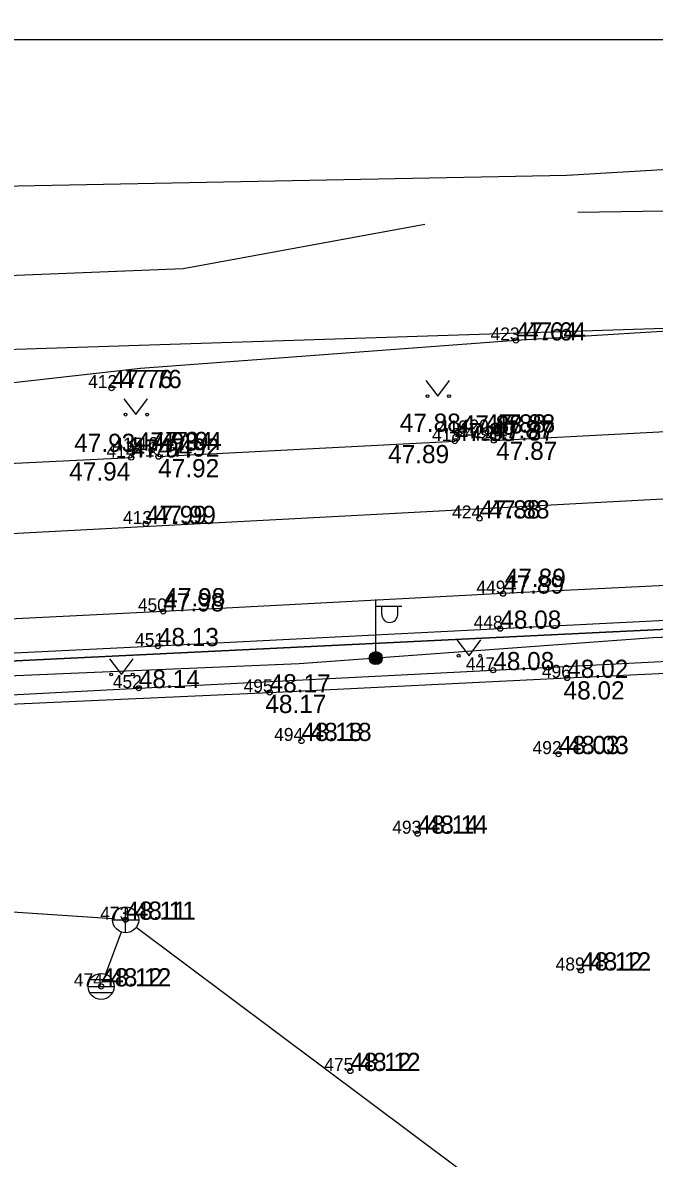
# Model space of a CAD drawing. Extents: x 640876 to 641418, y 6455595 to 6456085.
# Drawn here: x 641173.59 to 641197.83, y 6455977.11 to 6456020.73 of the extents above; entities that cross this region are included whole.
import ezdxf

# ---------------------------------------------------------------- set-up
doc = ezdxf.new("R2010")
doc.units = 0
for name, color, linetype in [('AED', 7, 'Continuous'), ('HALJASTUS', 7, 'Continuous'), ('KKAEV', 7, 'Continuous'), ('KORGUS', 7, 'Continuous'), ('MOOTKORG', 7, 'Continuous'), ('MOOTMPUNKT', 7, 'Continuous'), ('MOOTNR', 7, 'Continuous'), ('MOOTPIIR', 7, 'Continuous'), ('MPKAABEL', 7, 'Continuous'), ('PIIR', 7, 'Continuous'), ('POST', 7, 'Continuous'), ('SKKAEV', 7, 'Continuous'), ('SKTRASS', 7, 'Continuous'), ('TEE', 7, 'Continuous'), ('VEEKOGU', 7, 'Continuous'), ('VORMISTUS', 7, 'Continuous'), ('VTRASS', 7, 'Continuous')]:
    doc.layers.add(name, color=color, linetype=linetype)

msp = doc.modelspace()

# ---------------------------------------------------------------- linework, layer by layer
at = {"layer": 'AED'}
msp.add_lwpolyline([(641160.606, 6455994.253), (641178.047, 6455995.168), (641191.652, 6455995.856), (641207.752, 6455996.687), (641222.341, 6455997.449), (641221.765, 6455994.718), (641219.959, 6455985.906), (641217.708, 6455975.561), (641214.2, 6455967.017), (641207.311, 6455950.541), (641202.719, 6455939.647), (641198.916, 6455930.446)], dxfattribs=at)
at = {"layer": 'HALJASTUS'}
for p, q in [((641189.066, 6456006.992), (641189.53, 6456006.385)), ((641189.53, 6456006.385), (641189.975, 6456006.992)), ((641177.474, 6456006.282), (641177.938, 6456005.675)), ((641177.938, 6456005.675), (641178.383, 6456006.282)), ((641190.26, 6455997.018), (641190.723, 6455996.412)), ((641190.723, 6455996.412), (641191.169, 6455997.018)), ((641176.921, 6455996.297), (641177.385, 6455995.69)), ((641177.385, 6455995.69), (641177.83, 6455996.297))]:
    msp.add_line(p, q, dxfattribs=at)
for centre in [(641189.129, 6456006.385), (641189.957, 6456006.385), (641177.537, 6456005.675), (641178.365, 6456005.675), (641190.322, 6455996.412), (641191.151, 6455996.412), (641176.984, 6455995.69), (641177.813, 6455995.69)]:
    msp.add_circle(centre, 0.055, dxfattribs=at)
at = {"layer": 'KKAEV'}
for p, q in [((641177.541, 6455985.77), (641177.541, 6455986.77)), ((641177.041, 6455986.27), (641178.041, 6455986.27))]:
    msp.add_line(p, q, dxfattribs=at)
msp.add_circle((641177.541, 6455986.27), 0.5, dxfattribs=at)
at = {"layer": 'KORGUS'}
for centre in [(641192.523, 6456008.523), (641177, 6456006.695), (641190.441, 6456004.951), (641191.337, 6456004.985), (641190.176, 6456004.656), (641191.674, 6456004.679), (641177.755, 6456004.027), (641177.971, 6456004.29), (641178.538, 6456004.314), (641178.8, 6456004.062), (641178.314, 6456001.473), (641191.121, 6456001.685), (641192.028, 6455998.799), (641178.983, 6455998.116), (641194.491, 6455995.56), (641183.068, 6455995.004), (641184.29, 6455993.138), (641194.16, 6455992.634), (641188.749, 6455989.577), (641177.541, 6455986.27), (641195.021, 6455984.321), (641176.599, 6455983.71), (641186.165, 6455980.461)]:
    msp.add_circle(centre, 0.1, dxfattribs=at)
at = {"layer": 'MOOTMPUNKT'}
for centre in [(641192.523, 6456008.523), (641177, 6456006.695), (641190.441, 6456004.951), (641191.337, 6456004.985), (641190.176, 6456004.656), (641191.674, 6456004.679), (641177.755, 6456004.027), (641177.971, 6456004.29), (641178.538, 6456004.314), (641178.8, 6456004.062), (641178.314, 6456001.473), (641191.121, 6456001.685), (641192.028, 6455998.799), (641178.983, 6455998.116), (641191.921, 6455997.451), (641178.778, 6455996.781), (641191.652, 6455995.856), (641194.491, 6455995.56), (641178.047, 6455995.168), (641183.068, 6455995.004), (641184.29, 6455993.138), (641194.16, 6455992.634), (641188.749, 6455989.577), (641177.541, 6455986.27), (641195.021, 6455984.321), (641176.599, 6455983.71), (641186.165, 6455980.461)]:
    msp.add_circle(centre, 0.1, dxfattribs=at)
at = {"layer": 'MOOTPIIR'}
msp.add_lwpolyline([(641060.916, 6455895.936), (641100.061, 6455950.482), (641099.586, 6455952.159), (641069.132, 6455984.035), (641066.132, 6455988.623), (641076.463, 6456005.049), (641230.642, 6456010.048), (641237.36, 6455995.24), (641237.24, 6455992.81), (641236.258, 6455990.888), (641229.041, 6455971.315), (641203.026, 6455909.57), (641225.257, 6455906.847), (641239.512, 6455898.491), (641200.195, 6455851.697), (641192.016, 6455859.099), (641169.785, 6455829.138), (641192.025, 6455807.568), (641252.96, 6455758.075), (641231.388, 6455736.74), (641191.474, 6455775.975), (641152.419, 6455787.914), (641136.351, 6455788.307), (641049.066, 6455856.043)], dxfattribs=at)
at = {"layer": 'MPKAABEL'}
msp.add_lwpolyline([(641152.745, 6455994.399), (641157.936, 6455994.715), (641172.717, 6455995.627), (641184.197, 6455996.113), (641197.79, 6455997.111), (641207.568, 6455997.528), (641217.849, 6455998.12), (641221.671, 6455998.134)], dxfattribs=at)
at = {"layer": 'PIIR'}
for points in [[(640981.25, 6456014.49), (641018.11, 6456020.73), (641048.89, 6456017.91), (641071.8, 6456014.51), (641086.43, 6456012.78), (641194.48, 6456014.88), (641224.33, 6456016.64), (641234.96, 6456017.83), (641241.97, 6456004.88), (641237.36, 6455995.24), (641222.58, 6455998.61), (641084.84, 6455991.92), (641061.51, 6455993.34), (640998.61, 6455989.99), (640969.54, 6455988.44)], [(641222.58, 6455998.61), (641237.36, 6455995.24), (641235.34, 6455991.29), (641228.11, 6455971.68), (641220.5, 6455953.19), (641213.41, 6455936.25), (641201.58, 6455908.74), (641224.93, 6455905.88), (641191.87, 6455860.58), (641157.02, 6455885.66), (641160.91, 6455891.99), (641102.26, 6455951.82), (641074.95, 6455979.64), (641084.84, 6455991.92)]]:
    msp.add_lwpolyline(points, close=True, dxfattribs=at)
at = {"layer": 'POST'}
for p, q in [((641187.144, 6455996.571), (641187.144, 6455998.571)), ((641187.144, 6455998.321), (641188.144, 6455998.321)), ((641187.371, 6455998), (641187.371, 6455998.321)), ((641187.984, 6455998), (641187.984, 6455998.321)), ((641187.144, 6455996.321), (641187.144, 6455996.321))]:
    msp.add_line(p, q, dxfattribs=at)
for radius in [0.25, 0.225, 0.2, 0.175, 0.15, 0.125, 0.1, 0.075, 0.05, 0.025]:
    msp.add_circle((641187.144, 6455996.321), radius, dxfattribs=at)
msp.add_arc((641187.677, 6455998), 0.306, 180, 0, dxfattribs=at)
at = {"layer": 'SKKAEV'}
for p, q in [((641176.099, 6455983.71), (641177.099, 6455983.71)), ((641177.029, 6455983.96), (641176.169, 6455983.96)), ((641177.029, 6455983.46), (641176.169, 6455983.46))]:
    msp.add_line(p, q, dxfattribs=at)
msp.add_circle((641176.599, 6455983.71), 0.5, dxfattribs=at)
at = {"layer": 'SKTRASS'}
for points in [[(641177.042, 6455986.303), (641160.327, 6455987.415)], [(641177.368, 6455985.8), (641176.772, 6455984.179)], [(641190.389, 6455976.647), (641177.941, 6455985.97)]]:
    msp.add_lwpolyline(points, dxfattribs=at)
at = {"layer": 'TEE'}
for points in [[(641191.337, 6456004.985), (641191.674, 6456004.679), (641211.938, 6456005.745), (641220.1, 6456006.174), (641220.874, 6456006.265), (641222.296, 6456007.072), (641223.496, 6456008.075), (641224.979, 6456010.896)], [(641178.538, 6456004.314), (641178.8, 6456004.062), (641190.176, 6456004.656), (641190.441, 6456004.951)], [(641157.348, 6456003.221), (641157.594, 6456003.045), (641177.755, 6456004.027), (641177.971, 6456004.29)], [(641222.651, 6455997.98), (641222.677, 6455998.823), (641220.802, 6456000.252), (641207.904, 6455999.587), (641192.028, 6455998.799), (641178.983, 6455998.116), (641163.081, 6455997.316), (641161.565, 6455996.932), (641160.895, 6455996.447), (641160.425, 6455995.795), (641160.271, 6455995.032), (641160.279, 6455994.218), (641160.404, 6455993.367), (641161.226, 6455991.415), (641162.227, 6455990.048), (641167.668, 6455994.304), (641183.068, 6455995.004), (641194.491, 6455995.56), (641201.796, 6455995.908), (641207.259, 6455996.159), (641208.614, 6455995.025), (641219.562, 6455985.852), (641216.822, 6455976.794)], [(641222.264, 6455998.978), (641207.946, 6455998.252), (641191.921, 6455997.451), (641178.778, 6455996.781), (641160.679, 6455995.901)]]:
    msp.add_lwpolyline(points, dxfattribs=at)
at = {"layer": 'VEEKOGU'}
for points in [[(641194.894, 6456013.457), (641201.564, 6456013.556)], [(641129.494, 6456007.757), (641140.506, 6456009.297), (641141.425, 6456009.442), (641155.616, 6456010.605), (641165.969, 6456010.733), (641179.754, 6456011.289), (641189.024, 6456012.987)], [(641209.122, 6456009.547), (641192.523, 6456008.523), (641178.117, 6456007.452), (641160.284, 6456005.431), (641141.785, 6456004.469), (641139.156, 6456004.288), (641122.94, 6456003.612)]]:
    msp.add_lwpolyline(points, dxfattribs=at)
at = {"layer": 'VORMISTUS'}
msp.add_line((641035.115, 6456020.09), (641256.302, 6456020.09), dxfattribs=at)
at = {"layer": 'VTRASS'}
msp.add_lwpolyline([(641064.363, 6455995.75), (641076.979, 6455996.021), (641104.204, 6455997.462), (641127.864, 6455998.715), (641152.811, 6456000.037), (641188.143, 6456001.908), (641203.655, 6456002.73), (641225.036, 6456004.365)], dxfattribs=at)

# ---------------------------------------------------------------- texts
at = {"layer": 'KORGUS'}
for s, p in [('47.64', (641192.873, 6456008.523)), ('47.76', (641177.35, 6456006.695)), ('47.88', (641188.062, 6456005.014)), ('47.88', (641191.687, 6456004.985)), ('47.93', (641175.566, 6456004.241)), ('47.94', (641178.888, 6456004.314)), ('47.89', (641187.616, 6456003.808)), ('47.87', (641191.767, 6456003.937)), ('47.94', (641175.376, 6456003.143)), ('47.92', (641178.789, 6456003.267)), ('47.88', (641191.471, 6456001.685)), ('47.99', (641178.664, 6456001.473)), ('47.89', (641192.095, 6455999.057)), ('47.98', (641179.024, 6455998.309)), ('48.02', (641194.352, 6455994.732)), ('48.17', (641182.903, 6455994.212)), ('48.18', (641184.64, 6455993.138)), ('48.03', (641194.51, 6455992.634)), ('48.14', (641189.099, 6455989.577)), ('48.11', (641177.891, 6455986.27)), ('48.12', (641195.371, 6455984.321)), ('48.12', (641176.949, 6455983.71)), ('48.12', (641186.515, 6455980.461))]:
    msp.add_text(s, height=0.7, dxfattribs=at).set_placement(p)
at = {"layer": 'MOOTKORG'}
for s, p in [('47.64', (641192.523, 6456008.523)), ('47.76', (641177, 6456006.695)), ('47.89', (641190.176, 6456004.656)), ('47.88', (641190.441, 6456004.951)), ('47.88', (641191.337, 6456004.985)), ('47.87', (641191.582, 6456004.758)), ('47.87', (641191.674, 6456004.679)), ('47.93', (641177.971, 6456004.29)), ('47.94', (641178.538, 6456004.314)), ('47.94', (641177.755, 6456004.027)), ('47.92', (641178.8, 6456004.062)), ('47.88', (641191.121, 6456001.685)), ('47.99', (641178.314, 6456001.473)), ('47.89', (641192.028, 6455998.799)), ('47.98', (641178.983, 6455998.116)), ('48.08', (641191.921, 6455997.451)), ('48.13', (641178.778, 6455996.781)), ('48.08', (641191.652, 6455995.856)), ('48.02', (641194.491, 6455995.56)), ('48.14', (641178.047, 6455995.168)), ('48.17', (641183.068, 6455995.004)), ('48.18', (641184.29, 6455993.138)), ('48.03', (641194.16, 6455992.634)), ('48.14', (641188.749, 6455989.577)), ('48.11', (641177.541, 6455986.27)), ('48.12', (641195.021, 6455984.321)), ('48.12', (641176.599, 6455983.71)), ('48.12', (641186.165, 6455980.461))]:
    msp.add_text(s, height=0.7, dxfattribs=at).set_placement(p)
at = {"layer": 'MOOTNR'}
for s, p in [('423', (641191.548, 6456008.523)), ('412', (641176.1, 6456006.695)), ('419', (641189.566, 6456004.951)), ('420', (641190.362, 6456004.985)), ('418', (641189.301, 6456004.656)), ('422', (641190.582, 6456004.758)), ('421', (641190.799, 6456004.679)), ('414', (641176.805, 6456004.027)), ('415', (641177.071, 6456004.29)), ('416', (641177.663, 6456004.314)), ('417', (641177.9, 6456004.062)), ('413', (641177.439, 6456001.473)), ('424', (641190.071, 6456001.685)), ('449', (641191.003, 6455998.799)), ('450', (641178.008, 6455998.116)), ('448', (641190.897, 6455997.451)), ('451', (641177.903, 6455996.781)), ('447', (641190.602, 6455995.856)), ('496', (641193.517, 6455995.56)), ('452', (641177.047, 6455995.168)), ('495', (641182.068, 6455995.004)), ('494', (641183.24, 6455993.138)), ('492', (641193.16, 6455992.634)), ('493', (641187.774, 6455989.577)), ('473', (641176.566, 6455986.27)), ('489', (641194.046, 6455984.321)), ('474', (641175.55, 6455983.71)), ('475', (641185.165, 6455980.461))]:
    msp.add_text(s, height=0.5, dxfattribs=at).set_placement(p)

doc.saveas('drawing.dxf')
